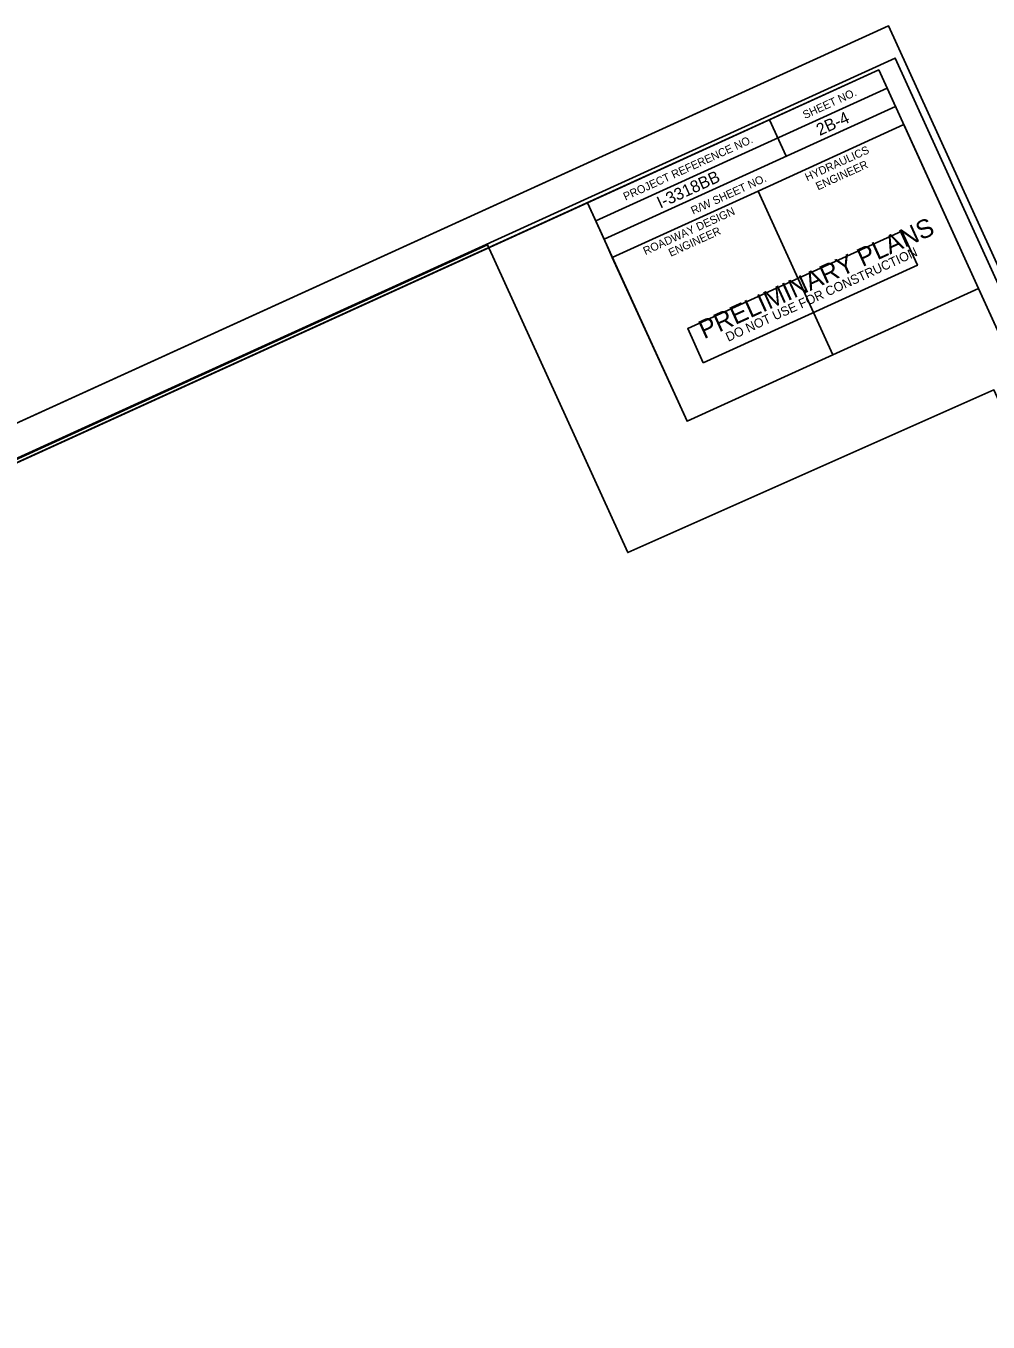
# Model space of a CAD drawing. Extents: x 2237908 to 2239894, y 658266 to 660035.
# Drawn here: x 2238901 to 2239502, y 659151 to 659961 of the extents above; entities that cross this region are included whole.
import ezdxf

# ---------------------------------------------------------------- set-up
doc = ezdxf.new("R2010")
doc.units = 0
for name, color, linetype in [('Sheet Clip Boundary CELL', 7, 'Continuous'), ('Sheet Cutting Line CELL', 7, 'Continuous'), ('Sheet Data Field CELL', 7, 'Continuous'), ('Sheet Plan CELL', 7, 'Continuous'), ('Sheet Plot Border Inside CELL', 7, 'Continuous'), ('Sheet Plot Border Outside CELL', 7, 'Continuous'), ('Sheet Sticker Preliminary CELL', 7, 'Continuous')]:
    doc.layers.add(name, color=color, linetype=linetype)

msp = doc.modelspace()

# ---------------------------------------------------------------- linework, layer by layer
at = {"layer": 'Sheet Clip Boundary CELL'}
msp.add_lwpolyline([(2238522.83, 658366.38), (2239853.4, 658970.14), (2239505.7, 659733.16), (2239276.88, 659631.46), (2239189.19, 659823.91), (2238087.44, 659321.86)], close=True, dxfattribs=at)
at = {"layer": 'Sheet Cutting Line CELL'}
msp.add_line((2239439.87, 659960.61), (2237907.93, 659262.53), dxfattribs=at)
at = {"layer": 'Sheet Plan CELL'}
for p, q in [((2239256.87, 659838.73), (2239438.92, 659921.67)), ((2239262.08, 659827.33), (2239444.1, 659910.3)), ((2239262.08, 659827.33), (2239444.1, 659910.3)), ((2239365.47, 659901.92), (2239375.88, 659879.2)), ((2239358.3, 659857.45), (2239404.95, 659755.12)), ((2239262.08, 659827.33), (2239267.26, 659815.96))]:
    msp.add_line(p, q, dxfattribs=at)
for points in [[(2239433.75, 659933.11), (2238068.75, 659311.1), (2238504.14, 658355.63), (2239869.12, 658977.62)], [(2239251.68, 659850.15), (2239433.75, 659933.11), (2239444.1, 659910.3), (2239262.08, 659827.33)], [(2239358.3, 659857.45), (2239449.29, 659898.92), (2239495.95, 659796.54), (2239404.96, 659755.07)], [(2239267.26, 659815.96), (2239358.3, 659857.45), (2239404.96, 659755.07), (2239313.92, 659713.61)], [(2238504.14, 658355.63), (2238068.74, 659311.07), (2239251.68, 659850.15), (2239313.92, 659713.61), (2239495.95, 659796.54), (2239869.12, 658977.62)]]:
    msp.add_lwpolyline(points, close=True, dxfattribs=at)
at = {"layer": 'Sheet Plot Border Inside CELL'}
msp.add_lwpolyline([(2238365.52, 658289.69), (2239881.52, 658980.52), (2239444.07, 659940.54), (2237928.05, 659249.72)], close=True, dxfattribs=at)
at = {"layer": 'Sheet Plot Border Outside CELL'}
msp.add_lwpolyline([(2238361.98, 658266.1), (2239893.93, 658964.18), (2239439.87, 659960.61), (2237907.93, 659262.53)], close=True, dxfattribs=at)
at = {"layer": 'Sheet Sticker Preliminary CELL'}
msp.add_lwpolyline([(2239324.11, 659750.1), (2239314.37, 659771.48), (2239448.14, 659832.44), (2239457.88, 659811.05)], close=True, dxfattribs=at)

# ---------------------------------------------------------------- texts
at = {"layer": 'Sheet Data Field CELL'}
for s, p in [('2B-4', (2239396.78, 659891.81)), ('I-3318BB', (2239297.22, 659846.37))]:
    msp.add_text(s, height=7.5, rotation=24.49795, dxfattribs=at).set_placement(p)
at = {"layer": 'Sheet Plan CELL'}
for s, height, p in [('SHEET NO.', 5, (2239387.62, 659902.39)), ('PROJECT REFERENCE NO.', 5.0001, (2239275.5, 659851.42)), ('HYDRAULICS', 5, (2239389.04, 659863.46)), ('ENGINEER', 5, (2239395.77, 659857.78)), ('R/W SHEET NO.', 5.0001, (2239317.76, 659842.6)), ('ROADWAY DESIGN', 5.0001, (2239287.92, 659817.35)), ('ENGINEER', 5, (2239303.77, 659816.29))]:
    msp.add_text(s, height=height, rotation=24.49795, dxfattribs=at).set_placement(p)
at = {"layer": 'Sheet Sticker Preliminary CELL'}
for s, height, p in [('PRELIMINARY PLANS', 11.52, (2239324.58, 659764.76)), ('DO NOT USE FOR CONSTRUCTION', 5.76, (2239339.69, 659763.18))]:
    msp.add_text(s, height=height, rotation=24.49794, dxfattribs=at).set_placement(p)

doc.saveas('drawing.dxf')
